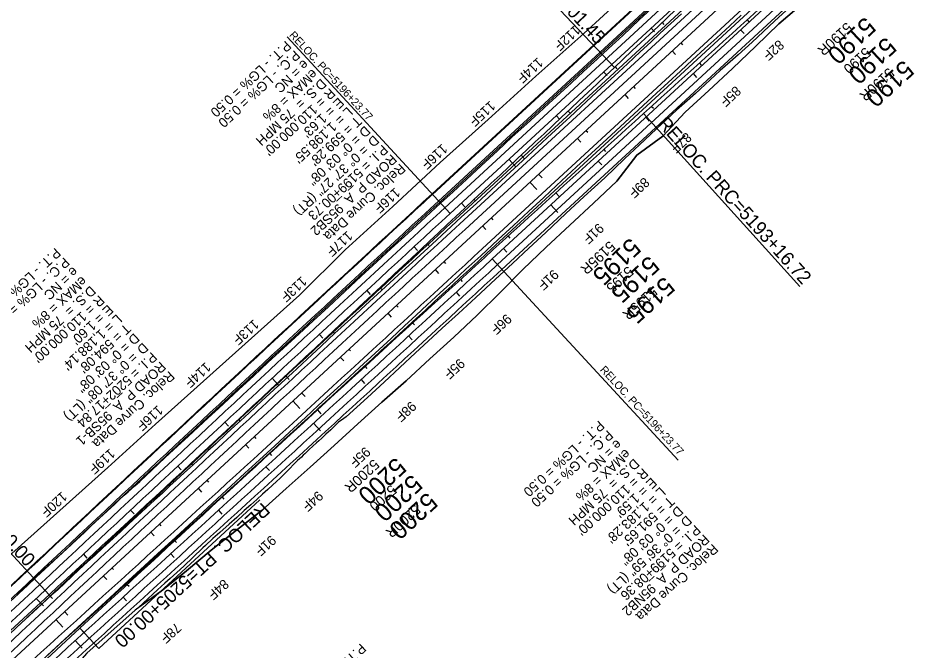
# Model space of a CAD drawing. Extents: x 2160876 to 2175990, y 601436 to 618246.
# Drawn here: x 2169726 to 2171138, y 611423 to 612405 of the extents above; entities that cross this region are included whole.
import ezdxf

# ---------------------------------------------------------------- set-up
doc = ezdxf.new("R2010")
doc.units = 0
for name, color, linetype in [('BNDY-ADJ', 7, 'Continuous'), ('BNDY-ADJ-TXT', 7, 'Continuous'), ('EX-UTIL-ELEC-TXT', 7, 'Continuous'), ('GN_Transparent 80', 7, 'Continuous'), ('RD_DTM_Major2', 7, 'Continuous'), ('RD_EX_BldgApp_Sign', 7, 'Continuous'), ('RD_EX_BldgApp_Steps', 7, 'Continuous'), ('RD_EX_DV_TX_Prop', 7, 'Continuous'), ('RD_EX_Fence_Gate', 7, 'Continuous'), ('RD_EX_RW', 7, 'Continuous'), ('RD_HC_Cl', 7, 'Continuous'), ('RD_HC_Data_Tic', 7, 'Continuous'), ('RD_HC_TX_Sta50', 7, 'Continuous'), ('RD_TX_RoadID', 7, 'Continuous')]:
    doc.layers.add(name, color=color, linetype=linetype)

msp = doc.modelspace()

# ---------------------------------------------------------------- linework, layer by layer
at = {"layer": 'BNDY-ADJ'}
msp.add_line((2172239.9, 613739.9), (2163704.8, 605858.6), dxfattribs=at)
at = {"layer": 'BNDY-ADJ-TXT'}
for p, q in [((2172207.3, 613775.1), (2170395.2, 612101.8)), ((2172272.5, 613704.6), (2170460.3, 612031.3))]:
    msp.add_line(p, q, dxfattribs=at)
for centre, start, end in [((2245020.2, 531286.6), 132.719474, 133.338342), ((2095835.3, 692846.5), 312.100607, 312.719474)]:
    msp.add_arc(centre, 110000, start, end, dxfattribs=at)
at = {"layer": 'EX-UTIL-ELEC-TXT'}
for p, q in [((2172179.3, 613805.5), (2170367.1, 612132.2)), ((2172180, 613804.8), (2170367.8, 612131.4)), ((2172199.2, 613784), (2170387, 612110.6)), ((2172207.3, 613775.1), (2170395.2, 612101.8)), ((2172215.5, 613766.3), (2170403.3, 612093)), ((2172264.3, 613713.4), (2170452.2, 612040.1)), ((2172272.5, 613704.6), (2170460.3, 612031.3)), ((2172261.1, 613677.8), (2170468.4, 612022.5))]:
    msp.add_line(p, q, dxfattribs=at)
for centre, radius, start, end in [((2245020.2, 531286.6), 110041.3, 132.719474, 133.338342), ((2245020.2, 531286.6), 110040.3, 132.719474, 133.338342), ((2245020.2, 531286.6), 110012, 132.719474, 133.338342), ((2245020.2, 531286.6), 110000, 132.719474, 133.338342), ((2245020.2, 531286.6), 109988, 132.719474, 133.338342), ((2095835.3, 692846.5), 109988, 312.100607, 312.719474), ((2095835.3, 692846.5), 110000, 312.100607, 312.719474), ((2095835.3, 692846.5), 110012, 312.100607, 312.719474)]:
    msp.add_arc(centre, radius, start, end, dxfattribs=at)
at = {"layer": 'GN_Transparent 80'}
for p, q in [((2172189.5, 613794.5), (2170377.3, 612121.1)), ((2172191, 613792.8), (2170378.9, 612119.4))]:
    msp.add_line(p, q, dxfattribs=at)
for radius in [110026.3, 110024]:
    msp.add_arc((2245020.2, 531286.6), radius, 132.719474, 133.338342, dxfattribs=at)
at = {"layer": 'RD_DTM_Major2'}
for p, q in [((2170739.1, 612354), (2170744.5, 612348.1)), ((2170665.6, 612286.2), (2170671, 612280.3)), ((2170592.1, 612218.3), (2170597.6, 612212.5)), ((2170518.7, 612150.5), (2170529.5, 612138.7)), ((2170445.2, 612082.7), (2170450.6, 612076.8)), ((2170371.7, 612014.8), (2170377.2, 612008.9)), ((2170298.3, 611947), (2170303.7, 611941.1)), ((2170224.8, 611879.1), (2170230.2, 611873.3)), ((2170151.3, 611811.3), (2170162.2, 611799.5)), ((2170077.9, 611743.5), (2170083.3, 611737.6)), ((2170004.4, 611675.6), (2170009.8, 611669.7)), ((2169930.9, 611607.8), (2169936.3, 611601.9)), ((2169857.5, 611539.9), (2169862.9, 611534.1)), ((2169784, 611472.1), (2169794.8, 611460.3))]:
    msp.add_line(p, q, dxfattribs=at)
at = {"layer": 'RD_EX_BldgApp_Sign'}
msp.add_line((2170418.2, 612076.8), (2171614.4, 613181.4), dxfattribs=at)
msp.add_arc((2245020.2, 531286.6), 109966, 132.719474, 133.338342, dxfattribs=at)
at = {"layer": 'RD_EX_BldgApp_Steps'}
for p, q in [((2172672.7, 614139.6), (2163700.6, 605854.7)), ((2170389.5, 612603.9), (2170649.6, 612328.2)), ((2170723.5, 612397.8), (2170726.2, 612394.9)), ((2170855.5, 612402.2), (2170858.2, 612399.2)), ((2170752.5, 612366.4), (2170755.2, 612363.5)), ((2170781.5, 612335), (2170784.1, 612332)), ((2170650.7, 612329.2), (2170653.4, 612326.3)), ((2170679, 612298.6), (2170681.7, 612295.6)), ((2170707.3, 612267.9), (2170710, 612264.9)), ((2170577.9, 612260.6), (2170580.7, 612257.7)), ((2170937.2, 611988.5), (2170694.9, 612256.7)), ((2170605.6, 612230.7), (2170608.3, 612227.8)), ((2170505.1, 612192.1), (2170510.6, 612186.2)), ((2170633.1, 612200.8), (2170635.8, 612197.9)), ((2170532.1, 612162.9), (2170537.5, 612157)), ((2170432.3, 612123.6), (2170435, 612120.7)), ((2170559, 612133.7), (2170564.4, 612127.8)), ((2170458.6, 612095), (2170461.3, 612092.1)), ((2170485, 612066.5), (2170487.7, 612063.5)), ((2170359.3, 612055.2), (2170362, 612052.3)), ((2170385.1, 612027.2), (2170387.9, 612024.3)), ((2170411, 611999.2), (2170413.7, 611996.3)), ((2170286.3, 611986.8), (2170289, 611983.9)), ((2170311.7, 611959.4), (2170314.4, 611956.4)), ((2170337, 611931.9), (2170339.7, 611928.9)), ((2170213.2, 611918.6), (2170216, 611915.6)), ((2170238.2, 611891.5), (2170240.9, 611888.6)), ((2170263.2, 611864.5), (2170265.9, 611861.5)), ((2170140.1, 611850.3), (2170145.6, 611844.5)), ((2170164.7, 611823.7), (2170170.2, 611817.8)), ((2170189.4, 611797), (2170194.8, 611791.1)), ((2169773.5, 611510.3), (2169524.2, 611780.4)), ((2170066.9, 611782.2), (2170069.6, 611779.3)), ((2170091.3, 611755.8), (2170094, 611752.9)), ((2170115.6, 611729.5), (2170118.3, 611726.5)), ((2169993.7, 611714.1), (2169996.4, 611711.2)), ((2170017.8, 611688), (2170020.5, 611685.1)), ((2170100.1, 611657.4), (2169850.5, 611426.9)), ((2170041.9, 611661.9), (2170044.6, 611658.9)), ((2169920.4, 611646.1), (2169923.1, 611643.2)), ((2169944.3, 611620.2), (2169947, 611617.2)), ((2169968.3, 611594.2), (2169971, 611591.2)), ((2169847, 611578.2), (2169849.7, 611575.2)), ((2169870.9, 611552.3), (2169873.6, 611549.4)), ((2169894.8, 611526.4), (2169897.5, 611523.5)), ((2169773.5, 611510.3), (2165657.1, 607709.2)), ((2169773.5, 611510.3), (2169779, 611504.4)), ((2169797.4, 611484.5), (2169802.8, 611478.6)), ((2169821.3, 611458.6), (2165682.4, 607636.8)), ((2169821.3, 611458.6), (2169850.5, 611426.9)), ((2169821.3, 611458.6), (2169826.7, 611452.8))]:
    msp.add_line(p, q, dxfattribs=at)
for centre, start, end in [((2246150.8, 532330.8), 132.719474, 133.343763), ((2096943.5, 693870), 312.103138, 312.719474), ((2095148.5, 692325.6), 312.719474, 313.343763), ((2244446.3, 530643.4), 132.103138, 132.719474)]:
    msp.add_arc(centre, 110000, start, end, dxfattribs=at)
at = {"layer": 'RD_EX_Fence_Gate'}
for p, q in [((2170675.7, 612448.7), (2170602.4, 612380.9)), ((2170602.4, 612380.9), (2170527.8, 612314.5)), ((2170527.8, 612314.5), (2170453.8, 612247.3)), ((2170453.8, 612247.3), (2170379.5, 612180.7)), ((2170379.5, 612180.7), (2170306.3, 612112.7)), ((2170306.3, 612112.7), (2170232.5, 612045.5)), ((2170232.5, 612045.5), (2170161.6, 611975.2)), ((2170161.6, 611975.2), (2170087.4, 611908.3)), ((2170087.4, 611908.3), (2170012.8, 611841.9)), ((2170012.8, 611841.9), (2169938.5, 611775.2)), ((2169938.5, 611775.2), (2169864.5, 611708)), ((2169864.5, 611708), (2169790, 611641.2)), ((2169790, 611641.2), (2169715.7, 611574.4))]:
    msp.add_line(p, q, dxfattribs=at)
for points in [[(2171170.3, 612624.1), (2171132.3, 612591.5), (2171093.8, 612559.5), (2171057.6, 612524.9), (2171020.5, 612491.5), (2170980.4, 612461.2), (2170942.5, 612428.5), (2170904.5, 612395.9), (2170868.6, 612361.2), (2170832.6, 612326.4), (2170796, 612292.4), (2170759.1, 612258.7), (2170724.9, 612221.9), (2170684.4, 612192.1), (2170653.3, 612152.1), (2170617.1, 612117.6), (2170580.6, 612083.5), (2170544, 612049.4), (2170507.9, 612014.8), (2170472.7, 611979.1), (2170437.2, 611943.9), (2170400.6, 611909.8), (2170363.7, 611876.2)], [(2170363.7, 611876.2), (2170327.1, 611842), (2170289.4, 611809.1), (2170252.3, 611775.7), (2170215.2, 611742.1), (2170178.2, 611708.5), (2170140.8, 611675.3), (2170104, 611641.4), (2170064.2, 611610.8), (2170025, 611579.5), (2169986.6, 611547.5), (2169947.4, 611516.2)], [(2169947.4, 611516.2), (2169906.8, 611486.5), (2169832.2, 611419.8), (2169766.1, 611344.1), (2169692.9, 611276), (2169621.4, 611206), (2169538.3, 611148.5), (2169467, 611078.3), (2169391.8, 611012.4), (2169318.6, 610944.2), (2169284.7, 610907.2), (2169174, 610806.1), (2169099.5, 610739.3), (2169025.5, 610672), (2168948.7, 610607.8), (2168874.4, 610540.9), (2168798.4, 610475.8), (2168741.5, 610390), (2168667.6, 610322.7), (2168592.4, 610252), (2168544.5, 610187.1)]]:
    msp.add_lwpolyline(points, dxfattribs=at)
at = {"layer": 'RD_EX_RW'}
for p, q in [((2170675.7, 612448.7), (2170602.4, 612380.9)), ((2170602.4, 612380.9), (2170527.8, 612314.5)), ((2170527.8, 612314.5), (2170453.8, 612247.3)), ((2170453.8, 612247.3), (2170379.5, 612180.7)), ((2170379.5, 612180.7), (2170306.3, 612112.7)), ((2170306.3, 612112.7), (2170232.5, 612045.5)), ((2170232.5, 612045.5), (2170161.6, 611975.2)), ((2170161.6, 611975.2), (2170087.4, 611908.3)), ((2170087.4, 611908.3), (2170012.8, 611841.9)), ((2170012.8, 611841.9), (2169938.5, 611775.2)), ((2169938.5, 611775.2), (2169864.5, 611708)), ((2169864.5, 611708), (2169790, 611641.2)), ((2169790, 611641.2), (2169715.7, 611574.4)), ((2169912.8, 611490.9), (2169947.4, 611516.2))]:
    msp.add_line(p, q, dxfattribs=at)
for points in [[(2170363.7, 611876.2), (2170400.6, 611909.8), (2170437.2, 611943.9), (2170472.7, 611979.1), (2170507.9, 612014.8), (2170544, 612049.4), (2170580.6, 612083.5), (2170617.1, 612117.6), (2170653.3, 612152.1), (2170684.4, 612192.1), (2170724.9, 612221.9), (2170759.1, 612258.7), (2170796, 612292.4), (2170832.6, 612326.4), (2170868.6, 612361.2), (2170904.5, 612395.9), (2170942.5, 612428.5), (2170980.4, 612461.2), (2171020.5, 612491.5), (2171057.6, 612524.9), (2171093.8, 612559.5), (2171132.3, 612591.5), (2171170.3, 612624.1)], [(2169723.7, 611510.8), (2169736, 611522.3), (2169748.9, 611534.3), (2169759.9, 611544.6), (2169772.2, 611555.9), (2169785.9, 611568.4), (2169800.4, 611581.3), (2169815.9, 611595.8), (2169828.3, 611607.2), (2169838.9, 611617.1), (2169851.6, 611629), (2169863.7, 611640.3), (2169874.8, 611650.5), (2169882.4, 611657.6), (2169890.2, 611664.7), (2169896.2, 611670.1), (2169906.5, 611679.5), (2169914, 611686.3), (2169923.9, 611695.6), (2169932.2, 611703.1), (2169943.1, 611713.4), (2169953.4, 611723.2), (2169972.4, 611740.7), (2169988.9, 611755.9), (2170004.8, 611770.5), (2170020.1, 611784.8), (2170036.2, 611799.5), (2170067.7, 611828.5), (2170090.8, 611850.1), (2170112.8, 611870.4), (2170136.8, 611892.7), (2170160.9, 611914.9), (2170183, 611935.4), (2170206.5, 611957), (2170231.9, 611980.7), (2170257.3, 612004.3), (2170281.4, 612026.6), (2170303.6, 612047.2), (2170329.4, 612070.9), (2170357.1, 612095.9), (2170380.4, 612117.8), (2170399.6, 612135.4), (2170420.8, 612154.8), (2170443, 612175.4), (2170468.3, 612199.1), (2170491.2, 612220.5), (2170514, 612241), (2170532.6, 612258.1), (2170548, 612272.2), (2170565.7, 612288.4), (2170583.1, 612304.2), (2170601.9, 612321.8), (2170623, 612341.3), (2170639.8, 612357), (2170662.5, 612378), (2170687.8, 612402), (2170713.1, 612425.2)], [(2170922.2, 612422.5), (2170897.7, 612400.1), (2170863.1, 612367.4), (2170841.3, 612347.9), (2170829.1, 612337.2), (2170813.8, 612323.5), (2170782.4, 612294.5), (2170775.1, 612287.9), (2170758.3, 612272.9), (2170745.9, 612262.1), (2170722.9, 612240.6), (2170688.6, 612208.2), (2170665.4, 612186.5), (2170634.6, 612157), (2170603, 612127.9), (2170574.5, 612101.7), (2170543.6, 612072.4), (2170516.8, 612047.9), (2170491.7, 612024.3), (2170465.3, 612000.1), (2170434.8, 611971.4), (2170408.1, 611946.8), (2170382.6, 611923.8), (2170360.9, 611903.8), (2170341.2, 611885.4), (2170317.3, 611862.9), (2170292.8, 611840.3), (2170266.8, 611816.4), (2170233.9, 611786.4), (2170230.4, 611783.9), (2170222.3, 611777.9), (2170216.6, 611772.2), (2170210.1, 611766.4), (2170202.7, 611759.6), (2170196.3, 611753.5), (2170191.5, 611748.9), (2170188.2, 611745.9), (2170176.8, 611735.6), (2170169.8, 611729), (2170167.2, 611726.7), (2170164.7, 611723.9), (2170158.7, 611718.7), (2170153.4, 611713.6), (2170145.4, 611705.4), (2170136.4, 611696), (2170131.1, 611690.6), (2170126.5, 611686.4), (2170112.5, 611673.4), (2170104.5, 611666.5), (2170095.5, 611658.3), (2170086, 611650.1), (2170075.9, 611641), (2170064.4, 611630.4), (2170052.8, 611619.7), (2170038.2, 611607), (2170027.5, 611597.4), (2170015.9, 611586.8), (2170012, 611583), (2170006.5, 611577.8), (2170001.6, 611573.1), (2169997.1, 611568.7), (2169982.5, 611554.8), (2169971.7, 611544.7), (2169961.1, 611535.8), (2169953.2, 611528.6), (2169941.6, 611517.9), (2169919.6, 611497.2), (2169912.8, 611490.9)], [(2170753.8, 612411.6), (2170736.9, 612396.3), (2170720.5, 612381.2), (2170706.1, 612367.4), (2170689.8, 612352.3), (2170669.9, 612334), (2170649.7, 612315.1), (2170629.3, 612296.6), (2170606.6, 612275.4), (2170580.4, 612251), (2170552.9, 612225.7), (2170530.6, 612205), (2170507.1, 612183.4), (2170481.9, 612160), (2170458.6, 612138.6), (2170435.7, 612117.3), (2170412.4, 612095.8), (2170389.4, 612074.8), (2170367.1, 612054.4), (2170342.2, 612031.3), (2170314.6, 612005.9), (2170288.5, 611982.2), (2170263.7, 611959.3), (2170241.1, 611938.1), (2170216.4, 611915.9), (2170195.2, 611895.8), (2170173.7, 611876), (2170150.2, 611854), (2170127.9, 611833.7), (2170103.4, 611811.3), (2170083.4, 611792.3), (2170070.1, 611780.1), (2170061.5, 611772.2), (2170049.2, 611760.8), (2170031.8, 611744.5), (2170019.8, 611733.5), (2170008.5, 611723), (2169997.2, 611712.6), (2169983, 611699.5), (2169970.4, 611688.1), (2169960.8, 611679.2), (2169949.4, 611668.2), (2169937.2, 611656.9), (2169924, 611645.1), (2169910.3, 611632.4), (2169896.6, 611619.7), (2169884.2, 611608.1), (2169867.1, 611592.5), (2169856.9, 611583), (2169844.9, 611571.9), (2169833.2, 611561.4), (2169819.9, 611548.9), (2169808.9, 611538.7), (2169797.8, 611528.2), (2169786.9, 611518.1), (2169778, 611510.2), (2169762.1, 611495.7), (2169749.4, 611483.7), (2169736.7, 611472.1), (2169722.9, 611459.4)], [(2169771.3, 611416.6), (2169791.5, 611435.3), (2169811.4, 611453.7), (2169837.9, 611478), (2169860.8, 611499.4), (2169882.3, 611519.2), (2169896.5, 611532.3), (2169921.4, 611555.2), (2169942, 611574.2), (2169963.9, 611594.2), (2169989.9, 611618.3), (2170011.7, 611638.7), (2170034.1, 611659.4), (2170055.6, 611679.1), (2170077.1, 611698.9), (2170099.7, 611719.6), (2170123.3, 611741.5), (2170146.4, 611762.7), (2170170.7, 611785.1), (2170190.7, 611803.9), (2170209.8, 611821.3), (2170231.2, 611841.1), (2170254.7, 611862.7), (2170278.7, 611885), (2170303.8, 611908), (2170324.5, 611927.3), (2170342.5, 611944.1), (2170359.4, 611960), (2170379.9, 611978.8), (2170399.8, 611996.8), (2170419.6, 612015.4), (2170442.5, 612036.2), (2170469.4, 612061.2), (2170493.2, 612083.2), (2170516.5, 612104.6), (2170540.4, 612126.7), (2170559.7, 612144.9), (2170591.1, 612173.9), (2170614.4, 612195.5), (2170637.9, 612216.8), (2170665.9, 612243), (2170694.2, 612269), (2170714.9, 612288.1), (2170733, 612304.8), (2170751.9, 612322.4), (2170770.8, 612340), (2170790, 612357.4), (2170808.4, 612374.2), (2170828.4, 612392.8), (2170846.1, 612409.2)], [(2169947.4, 611516.2), (2169986.6, 611547.5), (2170025, 611579.5), (2170064.2, 611610.8), (2170104, 611641.4), (2170140.8, 611675.3), (2170178.2, 611708.5), (2170215.2, 611742.1), (2170252.3, 611775.7), (2170289.4, 611809.1), (2170327.1, 611842), (2170363.7, 611876.2)]]:
    msp.add_lwpolyline(points, dxfattribs=at)
at = {"layer": 'RD_HC_Cl'}
for p, q in [((2170706.5, 612389.3), (2170711.9, 612383.4)), ((2170845.1, 612386.6), (2170850.5, 612380.7)), ((2170633, 612321.4), (2170638.5, 612315.6)), ((2170771.6, 612318.8), (2170777.1, 612312.9)), ((2170559.6, 612253.6), (2170565, 612247.7)), ((2170698.2, 612250.9), (2170703.6, 612245)), ((2170486.1, 612185.8), (2170497, 612174)), ((2170624.7, 612183.1), (2170630.1, 612177.2)), ((2170412.6, 612117.9), (2170418.1, 612112)), ((2170551.2, 612115.2), (2170562.1, 612103.5)), ((2170339.2, 612050.1), (2170344.6, 612044.2)), ((2170477.8, 612047.4), (2170483.2, 612041.5)), ((2170265.8, 611982.1), (2170271.2, 611976.3)), ((2170404.3, 611979.6), (2170409.7, 611973.7)), ((2170192.5, 611914.1), (2170197.9, 611908.3)), ((2170330.7, 611911.8), (2170336.2, 611905.9)), ((2170119.2, 611846.1), (2170130.1, 611834.4)), ((2170257.1, 611844.1), (2170262.5, 611838.2)), ((2170046, 611778), (2170051.4, 611772.1)), ((2170183.5, 611776.5), (2170194.3, 611764.7)), ((2169972.9, 611709.8), (2169978.3, 611703.9)), ((2170109.7, 611708.9), (2170115.1, 611703)), ((2169899.8, 611641.5), (2169905.2, 611635.7)), ((2170035.9, 611641.5), (2170041.3, 611635.6)), ((2169826.8, 611573.2), (2169832.2, 611567.3)), ((2169962.1, 611574), (2169967.5, 611568.1)), ((2169753.8, 611504.8), (2169764.7, 611493.1)), ((2169888.2, 611506.7), (2169893.6, 611500.8)), ((2169814.2, 611439.4), (2169824.9, 611427.6))]:
    msp.add_line(p, q, dxfattribs=at)
at = {"layer": 'RD_HC_TX_Sta50'}
for p, q in [((2170142.5, 612375.5), (2170395.2, 612101.8)), ((2170748.5, 611719.1), (2170460.3, 612031.3))]:
    msp.add_line(p, q, dxfattribs=at)
at = {"layer": 'RD_TX_RoadID'}
for p, q in [((2172191, 613792.8), (2170378.9, 612119.4)), ((2172287.4, 613688.4), (2170475.2, 612015.1)), ((2171794.8, 613364.3), (2170410.1, 612085.6)), ((2171830.1, 613326.1), (2170445.4, 612047.4))]:
    msp.add_line(p, q, dxfattribs=at)
for centre, radius, start, end in [((2245020.2, 531286.6), 110024, 132.719474, 133.338342), ((2245020.2, 531286.6), 109978, 132.719474, 133.338342), ((2095835.3, 692846.5), 109978, 312.100607, 312.719474), ((2095835.3, 692846.5), 110022, 312.100607, 312.719474)]:
    msp.add_arc(centre, radius, start, end, dxfattribs=at)

# ---------------------------------------------------------------- texts
at = {"layer": 'RD_EX_BldgApp_Steps'}
for s, height, rotation, p in [('RELOC. PRC=5193+01.45', 21, 313.3438, (2170391.4, 612607.7)), ('5190', 28, 223.1867, (2171038.2, 612408.2)), ('P.T. - LG% = 0.50', 15, 222.9386, (2170140.4, 612370.5)), ('5190', 28, 222.7195, (2171070.5, 612377)), ('P.C. - LG% = 0.50', 15, 222.9386, (2170154, 612355.9)), ('e = NC', 15, 222.9386, (2170167.7, 612341.2)), ('5190', 28, 222.2681, (2171097.8, 612341.2)), ('eMAX = 8%', 15, 222.9386, (2170181.3, 612326.6)), ('D.S. =  75 MPH', 15, 222.9386, (2170194.9, 612311.9)), ("R = 110,000.00'", 15, 222.9386, (2170208.5, 612297.3)), ("E = 1.63'", 15, 222.9386, (2170222.1, 612282.6)), ("L = 1,198.55'", 15, 222.9386, (2170235.8, 612268)), ("T = 599.28'", 15, 222.9386, (2170249.4, 612253.4)), ('RELOC. PRC=5193+16.72', 21, 312.1031, (2170715.1, 612240.3)), ('D = 0° 03\' 08"', 15, 222.9386, (2170263, 612238.7)), ('D', 15, 222.9386, (2170276.6, 612224.1)), ('P.I. = 5199+00.73', 15, 222.9386, (2170290.3, 612209.4)), ('    = 0° 37\' 27" (RT)', 15, 222.9386, (2170276.6, 612224.1)), ('ROAD P_A_95SB2', 15, 222.9386, (2170303.9, 612194.8)), ('Reloc. Curve Data', 15, 222.9386, (2170317.5, 612180.2)), ('5195', 28, 223.2403, (2170674.2, 612065.5)), ('5195', 28, 222.7195, (2170703.1, 612037.7)), ('5195', 28, 222.1986, (2170727.1, 612005.3)), ('RELOC. PT=5205+00.00', 21, 312.7195, (2169525.7, 611783)), ('P.T. - LG% = 0.50', 15, 222.6688, (2170625.8, 611781.4)), ('P.C. - LG% = 0.50', 15, 222.6688, (2170639.3, 611766.7)), ('e = NC', 15, 222.6688, (2170652.9, 611752)), ('eMAX = 8%', 15, 222.6688, (2170666.4, 611737.3)), ('5200', 28, 222.9799, (2170310.8, 611725.1)), ('D.S. =  75 MPH', 15, 222.6688, (2170680, 611722.6)), ("R = 110,000.00'", 15, 222.6688, (2170693.6, 611707.9)), ('5200', 28, 222.7195, (2170335.9, 611698.6)), ("E = 1.59'", 15, 222.6688, (2170707.1, 611693.2)), ("L = 1,183.28'", 15, 222.6688, (2170720.7, 611678.5)), ('5200', 28, 222.459, (2170359.6, 611670.8)), ("T = 591.65'", 15, 222.6688, (2170734.2, 611663.8)), ('RELOC. PT=5205+00.00', 21, 222.7195, (2170103.7, 611654.7)), ('D = 0° 03\' 08"', 15, 222.6688, (2170747.8, 611649.1)), ('D', 15, 222.6688, (2170761.3, 611634.4)), ('    = 0° 36\' 59" (LT)', 15, 222.6688, (2170761.3, 611634.4)), ('P.I. = 5199+08.36', 15, 222.6688, (2170774.9, 611619.7)), ('ROAD P_A_95NB2', 15, 222.6688, (2170788.4, 611605)), ('Reloc. Curve Data', 15, 222.6688, (2170802, 611590.2))]:
    msp.add_text(s, height=height, rotation=rotation, dxfattribs=at).set_placement(p)
at = {"layer": 'RD_EX_DV_TX_Prop'}
for s, p in [('5190', (2171038.1, 612360.6)), ('5195', (2170670.4, 612021.1)), ('5200', (2170303.4, 611682.2))]:
    msp.add_text(s, height=16, rotation=222.7195, dxfattribs=at).set_placement(p)
at = {"layer": 'RD_EX_Fence_Gate'}
for s, rotation, p in [('112F', 222.904, (2170588.5, 612394.8)), ('82F', 221.8113, (2170904.3, 612372)), ('114F', 222.8255, (2170530.8, 612344.6)), ('85F', 222.9825, (2170837.3, 612300.6)), ('115F', 222.747, (2170456.9, 612277.4)), ('87F', 222.904, (2170760.8, 612228.6)), ('116F', 222.6685, (2170382.6, 612210.8)), ('89F', 222.8255, (2170695.6, 612158.8)), ('116F', 222.59, (2170309.5, 612142.8)), ('91F', 222.747, (2170624.9, 612087.7)), ('117F', 222.5116, (2170235.7, 612075.6)), ('91F', 222.6685, (2170554.9, 612015.9)), ('113F', 222.4331, (2170164.8, 612005.2)), ('96F', 222.59, (2170482.1, 611947)), ('113F', 222.3546, (2170090.6, 611938.4)), ('114F', 222.2761, (2170016.1, 611872)), ('95F', 222.5116, (2170409.6, 611877.9)), ('116F', 222.2032, (2169941.9, 611805.2)), ('98F', 222.4331, (2170334.4, 611811.6)), ('119F', 222.2032, (2169867.8, 611738)), ('95F', 222.3546, (2170263.3, 611740.8)), ('120F', 222.2032, (2169793.4, 611671.3)), ('94F', 222.2761, (2170190, 611672.5)), ('91F', 222.2032, (2170117.2, 611603.6)), ('84F', 222.2032, (2170043.9, 611535.6)), ('78F', 222.2032, (2169970.2, 611468))]:
    msp.add_text(s, height=15, rotation=rotation, dxfattribs=at).set_placement(p)
at = {"layer": 'RD_HC_Data_Tic'}
for s, rotation, p in [('5190R', 222.7195, (2171009.3, 612399.4)), ('5190R', 222.7195, (2171074.4, 612328.9)), ('5195R', 222.7195, (2170642, 612060.2)), ('5195R', 222.7195, (2170707.1, 611989.7)), ('5200R', 222.9154, (2170276.3, 611721.8)), ('5200R', 222.5235, (2170340.2, 611651.6))]:
    msp.add_text(s, height=16, rotation=rotation, dxfattribs=at).set_placement(p)
at = {"layer": 'RD_HC_TX_Sta50'}
for s, height, rotation, p in [('RELOC. PC=5196+23.77', 12, 312.7195, (2170144.9, 612377.7)), ('P.T. - LG% = 0.50', 15, 222.7195, (2169783.2, 612049.3)), ('P.C. - LG% = 0.50', 15, 222.7195, (2169796.8, 612034.7)), ('e = NC', 15, 222.7195, (2169810.3, 612020)), ('eMAX = 8%', 15, 222.7195, (2169823.9, 612005.3)), ('D.S. =  75 MPH', 15, 222.7195, (2169837.5, 611990.6)), ("R = 110,000.00'", 15, 222.7195, (2169851, 611975.9)), ("E = 1.60'", 15, 222.7195, (2169864.6, 611961.2)), ("L = 1,188.14'", 15, 222.7195, (2169878.2, 611946.5)), ("T = 594.08'", 15, 222.7195, (2169891.7, 611931.8)), ('D = 0° 03\' 08"', 15, 222.7195, (2169905.3, 611917.1)), ('D', 15, 222.7195, (2169918.9, 611902.4)), ('    = 0° 37\' 08" (LT)', 15, 222.7195, (2169918.9, 611902.4)), ('P.I. = 5202+17.84', 15, 222.7195, (2169932.4, 611887.7)), ('ROAD P_A_95SB-1', 15, 222.7195, (2169946, 611873)), ('Reloc. Curve Data', 15, 222.7195, (2169959.6, 611858.3)), ('RELOC. PC=5196+23.77', 12, 312.7195, (2170626.6, 611858.7)), ('P.T. - LG% = 0.50', 15, 222.7195, (2170256.4, 611435.9))]:
    msp.add_text(s, height=height, rotation=rotation, dxfattribs=at).set_placement(p)

doc.saveas('drawing.dxf')
